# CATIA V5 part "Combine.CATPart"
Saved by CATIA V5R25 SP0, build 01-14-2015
Part number: Part1
Bounding box of the stored display mesh (mm): x 0 to 48.303, y -48.737 to 82.157, z 0 to 68.524
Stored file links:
  E:\cadcim\GSD_cat_v5-6r2014\Part_files\Combine.CATPart
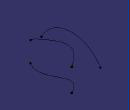
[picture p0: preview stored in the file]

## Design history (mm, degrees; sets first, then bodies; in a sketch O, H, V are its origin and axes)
Set1
  Sketch1 on xy-plane, origin (0, 0, 0), H (1, 0, 0), V (0, 1, 0)
    spline S1 through (48.3033, 66.5608) (25.8768, 40.109) (39.1026, 7.9068) (36.515, -36.6587)
  Sketch2 on yz-plane, origin (0, 0, 0), H (0, 1, 0), V (0, 0, 1)
    arc A1 centre (18.404, -5.761) radius 74.2849 from (-48.7369, 26.0251) to (82.1569, 32.368) cw
  Combine1: Curve1 Sketch2, Curve2 Sketch1
Body1 (main body)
